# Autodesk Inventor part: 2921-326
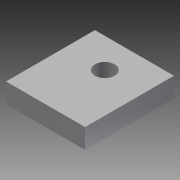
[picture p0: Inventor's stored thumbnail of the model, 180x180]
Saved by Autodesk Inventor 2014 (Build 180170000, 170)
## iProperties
Company: NHTSA/VRTC
Created: 2012-08
Part Number: 2921-326
Material: Steel, Mild
Document SubType Name: Modeling
Designer: Mike Vanvoorhis
Density: 7.86 g/cm^3
Mass: 244.96 g
Surface Area: 79.9527 cm^2
Volume: 31.1653 cm^3
Project: CHILD SIDE IMPACT SLED
Description: D-RING UPPER ANCHOR
Stock Number: BAR 50.8 (2") x 12.7 (1/2") x 57.2 (2 1/4")
Appearance: Steel
DESIGN DATE: 2012-11-05
Author: Dave Walker
Title: D-Ring Upper Anchor
Subject: Child Side Impact Sled
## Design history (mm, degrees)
sketch "Sketch1"
  geometry: L1 (0, 0)-(50.8, 0); L2 (50.8, 0)-(50.8, 12.7); L3 (50.8, 12.7)-(0, 12.7); L4 (0, 12.7)-(0, 0)
  constraints: 8 end point, 2 parallel, 1 horizontal, 1 perpendicular
  dimensions: "d0" = 50.8 distance of L3.end L2.end; "d1" = 12.7 distance of L2.end L1.end
extrude "Extrusion1" new body sketch "Sketch1" distance "d2" = 57.15; taper "d3" = 0 deg
sketch "Sketch2"
  geometry: L1 (50.8, 0)-(0, 0) reference; L2 (50.8, 0)-(50.8, 57.15) reference; L3 (25.4, 0)-(25.4, 38.1)
  constraints: 2 end point, 1 midpoint, 1 parallel
  dimensions: "d4" = 38.1 distance of L3.start L3.end
hole "Hole1" sketch "Sketch2" at (25.4, 38.1) diameter "d5" = 12.7; stored, may be unused: countersink angle "d9" = 82 deg, drill point angle "d11" = 118 deg; dims "d6" = 19.05, "d7" = 9.525, "d8" = 6.35, "d10" = 25.4
body "Solid1"
